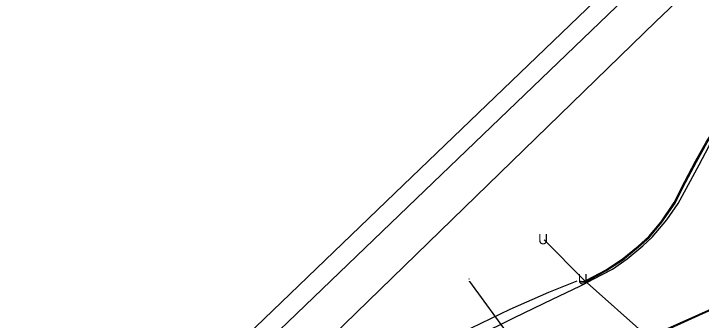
# Model space of a CAD drawing. Extents: x 1042086 to 1119166, y 1916606 to 1927565.
# Drawn here: x 1042427.1 to 1042832.5, y 1926260.8 to 1926441.4 of the extents above; entities that cross this region are included whole.
import ezdxf

# ---------------------------------------------------------------- set-up
doc = ezdxf.new("R2010")
doc.units = 0
for name, color, linetype in [('Default', 7, 'Continuous'), ('R_No Plot', 7, 'Continuous'), ('S_CROSS_DRAIN', 7, 'Continuous'), ('S_CURB', 7, 'Continuous'), ('S_DRG_PT_SYM', 7, 'Continuous'), ('S_EDGE_PAVEMENT', 7, 'Continuous'), ('S_SHOULDER', 7, 'Continuous'), ('S_UNDERGROUND_CABLE', 7, 'Continuous')]:
    doc.layers.add(name, color=color, linetype=linetype)

msp = doc.modelspace()

# ---------------------------------------------------------------- linework, layer by layer
at = {"layer": 'R_No Plot'}
for points in [[(1044190.35, 1927564.54), (1043981.84, 1927438.75), (1043847.5, 1927351.11), (1043782.09, 1927308.44), (1043697.07, 1927249.19), (1043570.31, 1927157.92), (1043487.46, 1927093.8), (1043395.3, 1927021.04), (1043346.81, 1926980.95), (1043282.61, 1926927.86), (1043155.48, 1926815.57), (1043010.71, 1926680.15), (1042651.83, 1926335.68), (1042368.92, 1926064.14), (1042086.02, 1925792.6)], [(1044196.03, 1927555.13), (1043987.69, 1927429.43), (1043853.51, 1927341.9), (1043788.24, 1927299.32), (1043703.43, 1927240.21), (1043576.89, 1927149.1), (1043494.23, 1927085.13), (1043402.21, 1927012.49), (1043353.82, 1926972.48), (1043289.76, 1926919.5), (1043162.88, 1926807.43), (1043018.28, 1926672.16), (1042659.44, 1926327.74), (1042376.54, 1926056.21), (1042093.64, 1925784.67)], [(1042478.4, 1926119.04), (1042593.51, 1926230.8), (1042805.67, 1926436.78), (1043162.99, 1926776.23), (1043224.64, 1926831.91), (1043251.28, 1926855.08), (1043316.64, 1926911.14), (1043414.38, 1926992.32), (1043498.45, 1927058.67), (1043606.9, 1927141.54), (1043742.89, 1927238.47), (1043809.93, 1927284.87), (1043730.4, 1927218.11), (1043687.56, 1927181.41)]]:
    msp.add_lwpolyline(points, dxfattribs=at)
at = {"layer": 'S_CROSS_DRAIN'}
msp.add_line((1042695.76, 1926283.73), (1042757.39, 1926199.15), dxfattribs=at)
at = {"layer": 'S_CURB'}
for points in [[(1042760.54, 1926284.08), (1042762.85, 1926283.75), (1042764.86, 1926284.5), (1042775.99, 1926290.39), (1042785.8, 1926296.8), (1042795.18, 1926304.46), (1042801.46, 1926310.13), (1042808.75, 1926318.85), (1042816.5, 1926330.12), (1042822.73, 1926342.66), (1042829.01, 1926354.53), (1042835.41, 1926365.84), (1042842.54, 1926377.1), (1042850.24, 1926388.05), (1042858.18, 1926398.51), (1042866.27, 1926407.86), (1042875.28, 1926417.09), (1042884.47, 1926425.63), (1042896.88, 1926436.86), (1042897.75, 1926438.32), (1042897.69, 1926440.93)], [(1042695.94, 1926214.35), (1042695.97, 1926213.78), (1042696.59, 1926213.58), (1042708.32, 1926209.73), (1042709.56, 1926210.3), (1042734.31, 1926220.89), (1042758.98, 1926231.82), (1042784.56, 1926243.21), (1042805.68, 1926252.32), (1042831.22, 1926263.78), (1042854.05, 1926273.96)]]:
    msp.add_lwpolyline(points, dxfattribs=at)
at = {"layer": 'S_DRG_PT_SYM'}
for points in [[(1042695.59, 1926285.15), (1042695.59, 1926285.2), (1042695.59, 1926285.15), (1042695.54, 1926285.15), (1042695.59, 1926285.15), (1042695.59, 1926285.1), (1042695.59, 1926285.15), (1042695.64, 1926285.15)], [(1042695.76, 1926283.73), (1042695.76, 1926283.78), (1042695.76, 1926283.73), (1042695.71, 1926283.73), (1042695.76, 1926283.73), (1042695.76, 1926283.68), (1042695.76, 1926283.73), (1042695.81, 1926283.73)]]:
    msp.add_lwpolyline(points, dxfattribs=at)
at = {"layer": 'S_EDGE_PAVEMENT'}
for points in [[(1042768.77, 1926285), (1042780.18, 1926290.98), (1042788.87, 1926296.94), (1042798.1, 1926304.59), (1042803.61, 1926309.87), (1042812.13, 1926319.96), (1042818.79, 1926329.64), (1042824.89, 1926340.76), (1042831.17, 1926352.4), (1042836.94, 1926363.27), (1042844.83, 1926376.03), (1042853.65, 1926388.29), (1042861.47, 1926397.76), (1042871.62, 1926408.9), (1042880.61, 1926418.18), (1042891.87, 1926428.94), (1042898.4, 1926434.87)], [(1042478.4, 1926119.04), (1042498.1, 1926134.43), (1042518.07, 1926149.47), (1042540.9, 1926165.27), (1042560.98, 1926178.59), (1042584.41, 1926192.02), (1042606.45, 1926203.82), (1042610.43, 1926206.01), (1042632.63, 1926217.51), (1042654.93, 1926228.83), (1042677.26, 1926240.1), (1042699.67, 1926251.2), (1042722.25, 1926262.4), (1042744.82, 1926273.18), (1042760.77, 1926281), (1042763.22, 1926282.13), (1042768.77, 1926285)], [(1042696.32, 1926214.25), (1042696.7, 1926214.11), (1042708.44, 1926210.37), (1042709.68, 1926210.89), (1042734, 1926221.56), (1042758.78, 1926232.26), (1042784.32, 1926243.73), (1042805.41, 1926252.91), (1042831.04, 1926264.16), (1042853.86, 1926274.37)]]:
    msp.add_lwpolyline(points, dxfattribs=at)
at = {"layer": 'S_SHOULDER'}
for points in [[(1042760.76, 1926283.66), (1042763.09, 1926283.29), (1042765.18, 1926283.87), (1042776.22, 1926289.95), (1042786.05, 1926296.32), (1042795.4, 1926304.02), (1042801.97, 1926309.87), (1042809.29, 1926318.58), (1042817.06, 1926329.84), (1042823.34, 1926342.36), (1042829.63, 1926354.22), (1042835.92, 1926365.59), (1042842.98, 1926376.88), (1042850.59, 1926387.7), (1042858.54, 1926398.17), (1042866.61, 1926407.53), (1042875.66, 1926416.72), (1042884.8, 1926425.32), (1042897.27, 1926436.48), (1042898.15, 1926437.93), (1042898.15, 1926440.49)], [(1042607.52, 1926211.41), (1042629.65, 1926223.03), (1042651.94, 1926234.38), (1042674.28, 1926245.62), (1042696.91, 1926256.32), (1042719.69, 1926267.36), (1042742.62, 1926277.43), (1042759.24, 1926283.96)]]:
    msp.add_lwpolyline(points, dxfattribs=at)
at = {"layer": 'S_UNDERGROUND_CABLE'}
for p, q in [((1042739.93, 1926308.13), (1042763.32, 1926284.54)), ((1042763.32, 1926284.54), (1042801.55, 1926250.65))]:
    msp.add_line(p, q, dxfattribs=at)

# ---------------------------------------------------------------- texts
at = {"layer": 'Default'}
for p in [(1042736.3, 1926305.59), (1042759.69, 1926281.99)]:
    msp.add_text('U', height=6, rotation=360, dxfattribs=at).set_placement(p)

doc.saveas('drawing.dxf')
